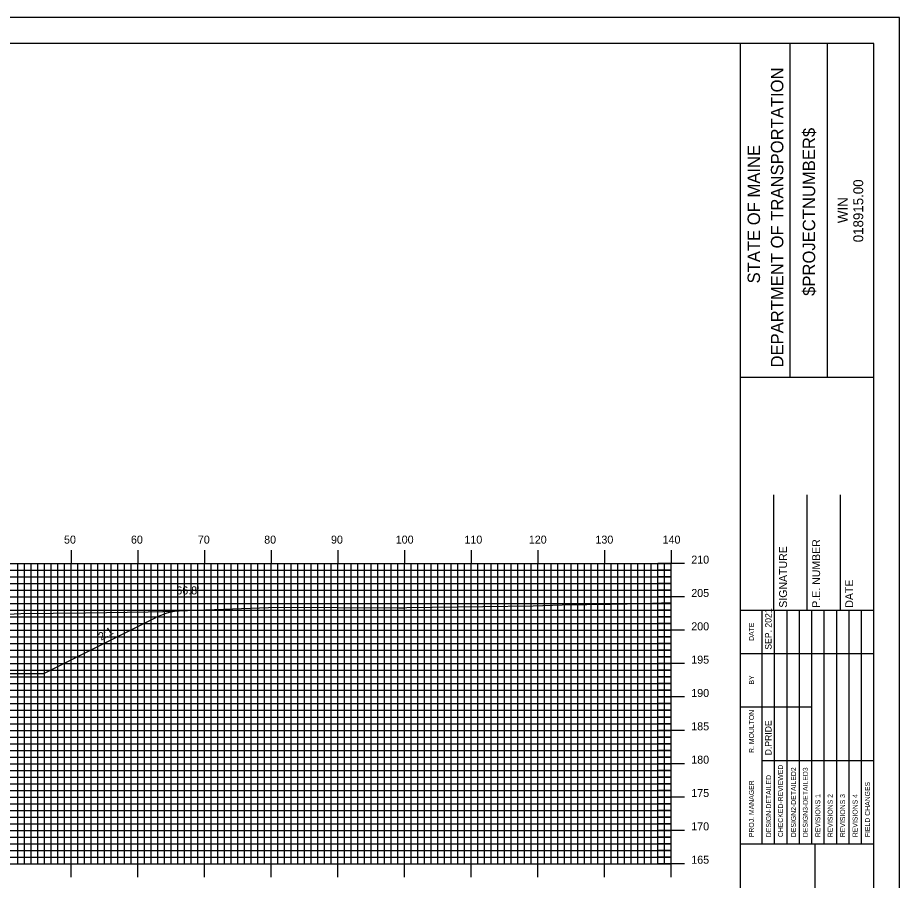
# Model space of a CAD drawing. Extents: x 1795240 to 1795583, y 442591 to 442811.
# Drawn here: x 1795447.3 to 1795579.6, y 442681.2 to 442810.5 of the extents above; entities that cross this region are included whole.
import ezdxf

# ---------------------------------------------------------------- set-up
doc = ezdxf.new("R2010")
doc.units = 0
for name, color, linetype in [('ANNOTATION', 7, 'Continuous'), ('BORDER', 7, 'Continuous'), ('D_Roadway_Centerline', 7, 'Continuous'), ('D_Roadway_SlopeLines', 7, 'Continuous'), ('D_Text_Standard', 7, 'Continuous'), ('H_V ANNOTATION', 7, 'Continuous'), ('MAJOR', 7, 'Continuous'), ('MINOR', 7, 'Continuous'), ('PLOT BOUNDARY', 7, 'Continuous'), ('S_Roadway_Centerline', 7, 'Continuous')]:
    doc.layers.add(name, color=color, linetype=linetype)

msp = doc.modelspace()

# ---------------------------------------------------------------- linework, layer by layer
at = {"layer": 'BORDER'}
for p, q in [((1795555.77, 442596.67), (1795555.77, 442806.67)), ((1795563.22, 442756.66), (1795563.22, 442806.66)), ((1795568.81, 442756.66), (1795568.81, 442806.66)), ((1795555.77, 442756.65), (1795575.77, 442756.65)), ((1795560.77, 442721.67), (1795560.77, 442738.97)), ((1795565.77, 442721.67), (1795565.77, 442738.97)), ((1795570.77, 442721.67), (1795570.77, 442738.97)), ((1795555.77, 442721.67), (1795575.77, 442721.67)), ((1795555.77, 442686.67), (1795575.77, 442686.67)), ((1795566.95, 442616.67), (1795566.95, 442686.67))]:
    msp.add_line(p, q, dxfattribs=at)
msp.add_lwpolyline([(1795255.77, 442596.67), (1795575.77, 442596.67), (1795575.77, 442806.67), (1795255.77, 442806.67)], close=True, dxfattribs=at)
for points in [[(1795559, 442715.17), (1795559, 442721.67)], [(1795560.86, 442686.68), (1795560.86, 442721.67)], [(1795562.72, 442721.67), (1795562.72, 442686.68)], [(1795564.59, 442686.68), (1795564.59, 442721.67)], [(1795566.45, 442686.68), (1795566.45, 442721.67)], [(1795568.31, 442686.68), (1795568.31, 442721.67)], [(1795570.18, 442686.68), (1795570.18, 442721.67)], [(1795572.04, 442686.68), (1795572.04, 442721.67)], [(1795573.9, 442686.68), (1795573.9, 442721.67)], [(1795559, 442686.68), (1795559, 442720.26)], [(1795555.77, 442715.17), (1795575.77, 442715.17)], [(1795555.77, 442707.17), (1795559, 442707.17)], [(1795559, 442707.17), (1795566.45, 442707.17)], [(1795559, 442699.17), (1795575.77, 442699.17)]]:
    msp.add_lwpolyline(points, dxfattribs=at)
at = {"layer": 'D_Roadway_Centerline'}
msp.add_arc((1795472.56, 442711.63), 10, 92.1706, 116.5651, dxfattribs=at)
at = {"layer": 'D_Roadway_SlopeLines'}
msp.add_line((1795451.28, 442712.17), (1795468.09, 442720.57), dxfattribs=at)
msp.add_lwpolyline([(1795444.37, 442708.53), (1795445.28, 442712.17), (1795451.28, 442712.17)], dxfattribs=at)
at = {"layer": 'MAJOR'}
for p, q in [((1795455.37, 442730.67), (1795455.37, 442728.67)), ((1795465.37, 442730.67), (1795465.37, 442728.67)), ((1795475.37, 442730.67), (1795475.37, 442728.67)), ((1795485.37, 442730.67), (1795485.37, 442728.67)), ((1795495.37, 442730.67), (1795495.37, 442728.67)), ((1795505.37, 442730.67), (1795505.37, 442728.67)), ((1795515.37, 442730.67), (1795515.37, 442728.67)), ((1795525.37, 442730.67), (1795525.37, 442728.67)), ((1795535.37, 442730.67), (1795535.37, 442728.67)), ((1795545.37, 442730.67), (1795545.37, 442728.67)), ((1795265.37, 442728.67), (1795545.37, 442728.67)), ((1795265.37, 442728.67), (1795545.37, 442728.67)), ((1795455.37, 442683.67), (1795455.37, 442728.67)), ((1795465.37, 442683.67), (1795465.37, 442728.67)), ((1795475.37, 442683.67), (1795475.37, 442728.67)), ((1795485.37, 442683.67), (1795485.37, 442728.67)), ((1795495.37, 442683.67), (1795495.37, 442728.67)), ((1795505.37, 442683.67), (1795505.37, 442728.67)), ((1795515.37, 442683.67), (1795515.37, 442728.67)), ((1795525.37, 442683.67), (1795525.37, 442728.67)), ((1795535.37, 442683.67), (1795535.37, 442728.67)), ((1795547.37, 442728.67), (1795543.36, 442728.67)), ((1795545.37, 442683.67), (1795545.37, 442728.67)), ((1795545.37, 442683.67), (1795545.37, 442728.67)), ((1795265.37, 442723.67), (1795545.37, 442723.67)), ((1795547.37, 442723.67), (1795543.36, 442723.67)), ((1795265.37, 442718.67), (1795545.37, 442718.67)), ((1795547.37, 442718.67), (1795543.36, 442718.67)), ((1795265.37, 442713.67), (1795545.37, 442713.67)), ((1795547.37, 442713.67), (1795543.36, 442713.67)), ((1795265.37, 442708.67), (1795545.37, 442708.67)), ((1795547.37, 442708.67), (1795543.36, 442708.67)), ((1795265.37, 442703.67), (1795545.37, 442703.67)), ((1795547.37, 442703.67), (1795543.36, 442703.67)), ((1795265.37, 442698.67), (1795545.37, 442698.67)), ((1795547.37, 442698.67), (1795543.36, 442698.67)), ((1795265.37, 442693.67), (1795545.37, 442693.67)), ((1795547.37, 442693.67), (1795543.36, 442693.67)), ((1795265.37, 442688.67), (1795545.37, 442688.67)), ((1795547.37, 442688.67), (1795543.36, 442688.67)), ((1795265.37, 442683.67), (1795545.37, 442683.67)), ((1795265.37, 442683.67), (1795545.37, 442683.67)), ((1795455.37, 442681.66), (1795455.37, 442683.67)), ((1795465.37, 442681.66), (1795465.37, 442683.67)), ((1795475.37, 442681.66), (1795475.37, 442683.67)), ((1795485.37, 442681.66), (1795485.37, 442683.67)), ((1795495.37, 442681.66), (1795495.37, 442683.67)), ((1795505.37, 442681.66), (1795505.37, 442683.67)), ((1795515.37, 442681.66), (1795515.37, 442683.67)), ((1795525.37, 442681.66), (1795525.37, 442683.67)), ((1795535.37, 442681.66), (1795535.37, 442683.67)), ((1795547.37, 442683.67), (1795543.36, 442683.67)), ((1795545.37, 442681.66), (1795545.37, 442683.67))]:
    msp.add_line(p, q, dxfattribs=at)
at = {"layer": 'MINOR'}
for p, q in [((1795447.37, 442683.67), (1795447.37, 442728.67)), ((1795448.37, 442683.67), (1795448.37, 442728.67)), ((1795449.37, 442683.67), (1795449.37, 442728.67)), ((1795450.37, 442683.67), (1795450.37, 442728.67)), ((1795451.37, 442683.67), (1795451.37, 442728.67)), ((1795452.37, 442683.67), (1795452.37, 442728.67)), ((1795453.37, 442683.67), (1795453.37, 442728.67)), ((1795454.37, 442683.67), (1795454.37, 442728.67)), ((1795456.37, 442683.67), (1795456.37, 442728.67)), ((1795457.37, 442683.67), (1795457.37, 442728.67)), ((1795458.37, 442683.67), (1795458.37, 442728.67)), ((1795459.37, 442683.67), (1795459.37, 442728.67)), ((1795460.37, 442683.67), (1795460.37, 442728.67)), ((1795461.37, 442683.67), (1795461.37, 442728.67)), ((1795462.37, 442683.67), (1795462.37, 442728.67)), ((1795463.37, 442683.67), (1795463.37, 442728.67)), ((1795464.37, 442683.67), (1795464.37, 442728.67)), ((1795466.37, 442683.67), (1795466.37, 442728.67)), ((1795467.37, 442683.67), (1795467.37, 442728.67)), ((1795468.37, 442683.67), (1795468.37, 442728.67)), ((1795469.37, 442683.67), (1795469.37, 442728.67)), ((1795470.37, 442683.67), (1795470.37, 442728.67)), ((1795471.37, 442683.67), (1795471.37, 442728.67)), ((1795472.37, 442683.67), (1795472.37, 442728.67)), ((1795473.37, 442683.67), (1795473.37, 442728.67)), ((1795474.37, 442683.67), (1795474.37, 442728.67)), ((1795476.37, 442683.67), (1795476.37, 442728.67)), ((1795477.37, 442683.67), (1795477.37, 442728.67)), ((1795478.37, 442683.67), (1795478.37, 442728.67)), ((1795479.37, 442683.67), (1795479.37, 442728.67)), ((1795480.37, 442683.67), (1795480.37, 442728.67)), ((1795481.37, 442683.67), (1795481.37, 442728.67)), ((1795482.37, 442683.67), (1795482.37, 442728.67)), ((1795483.37, 442683.67), (1795483.37, 442728.67)), ((1795484.37, 442683.67), (1795484.37, 442728.67)), ((1795486.37, 442683.67), (1795486.37, 442728.67)), ((1795487.37, 442683.67), (1795487.37, 442728.67)), ((1795488.37, 442683.67), (1795488.37, 442728.67)), ((1795489.37, 442683.67), (1795489.37, 442728.67)), ((1795490.37, 442683.67), (1795490.37, 442728.67)), ((1795491.37, 442683.67), (1795491.37, 442728.67)), ((1795492.37, 442683.67), (1795492.37, 442728.67)), ((1795493.37, 442683.67), (1795493.37, 442728.67)), ((1795494.37, 442683.67), (1795494.37, 442728.67)), ((1795496.37, 442683.67), (1795496.37, 442728.67)), ((1795497.37, 442683.67), (1795497.37, 442728.67)), ((1795498.37, 442683.67), (1795498.37, 442728.67)), ((1795499.37, 442683.67), (1795499.37, 442728.67)), ((1795500.37, 442683.67), (1795500.37, 442728.67)), ((1795501.37, 442683.67), (1795501.37, 442728.67)), ((1795502.37, 442683.67), (1795502.37, 442728.67)), ((1795503.37, 442683.67), (1795503.37, 442728.67)), ((1795504.37, 442683.67), (1795504.37, 442728.67)), ((1795506.37, 442683.67), (1795506.37, 442728.67)), ((1795507.37, 442683.67), (1795507.37, 442728.67)), ((1795508.37, 442683.67), (1795508.37, 442728.67)), ((1795509.37, 442683.67), (1795509.37, 442728.67)), ((1795510.37, 442683.67), (1795510.37, 442728.67)), ((1795511.37, 442683.67), (1795511.37, 442728.67)), ((1795512.37, 442683.67), (1795512.37, 442728.67)), ((1795513.37, 442683.67), (1795513.37, 442728.67)), ((1795514.37, 442683.67), (1795514.37, 442728.67)), ((1795516.37, 442683.67), (1795516.37, 442728.67)), ((1795517.37, 442683.67), (1795517.37, 442728.67)), ((1795518.37, 442683.67), (1795518.37, 442728.67)), ((1795519.37, 442683.67), (1795519.37, 442728.67)), ((1795520.37, 442683.67), (1795520.37, 442728.67)), ((1795521.37, 442683.67), (1795521.37, 442728.67)), ((1795522.37, 442683.67), (1795522.37, 442728.67)), ((1795523.37, 442683.67), (1795523.37, 442728.67)), ((1795524.37, 442683.67), (1795524.37, 442728.67)), ((1795526.37, 442683.67), (1795526.37, 442728.67)), ((1795527.37, 442683.67), (1795527.37, 442728.67)), ((1795528.37, 442683.67), (1795528.37, 442728.67)), ((1795529.37, 442683.67), (1795529.37, 442728.67)), ((1795530.37, 442683.67), (1795530.37, 442728.67)), ((1795531.37, 442683.67), (1795531.37, 442728.67)), ((1795532.37, 442683.67), (1795532.37, 442728.67)), ((1795533.37, 442683.67), (1795533.37, 442728.67)), ((1795534.37, 442683.67), (1795534.37, 442728.67)), ((1795536.37, 442683.67), (1795536.37, 442728.67)), ((1795537.37, 442683.67), (1795537.37, 442728.67)), ((1795538.37, 442683.67), (1795538.37, 442728.67)), ((1795539.37, 442683.67), (1795539.37, 442728.67)), ((1795540.37, 442683.67), (1795540.37, 442728.67)), ((1795541.37, 442683.67), (1795541.37, 442728.67)), ((1795542.37, 442683.67), (1795542.37, 442728.67)), ((1795543.37, 442683.67), (1795543.37, 442728.67)), ((1795544.37, 442683.67), (1795544.37, 442728.67)), ((1795265.37, 442727.67), (1795545.37, 442727.67)), ((1795545.37, 442727.67), (1795543.36, 442727.67)), ((1795265.37, 442726.67), (1795545.37, 442726.67)), ((1795545.37, 442726.67), (1795543.36, 442726.67)), ((1795265.37, 442725.67), (1795545.37, 442725.67)), ((1795545.37, 442725.67), (1795543.36, 442725.67)), ((1795265.37, 442724.67), (1795545.37, 442724.67)), ((1795545.37, 442724.67), (1795543.36, 442724.67)), ((1795265.37, 442722.67), (1795545.37, 442722.67)), ((1795545.37, 442722.67), (1795543.36, 442722.67)), ((1795265.37, 442721.67), (1795545.37, 442721.67)), ((1795545.37, 442721.67), (1795543.36, 442721.67)), ((1795265.37, 442720.67), (1795545.37, 442720.67)), ((1795265.37, 442719.67), (1795545.37, 442719.67)), ((1795545.37, 442720.67), (1795543.36, 442720.67)), ((1795545.37, 442719.67), (1795543.36, 442719.67)), ((1795265.37, 442717.67), (1795545.37, 442717.67)), ((1795545.37, 442717.67), (1795543.36, 442717.67)), ((1795265.37, 442716.67), (1795545.37, 442716.67)), ((1795265.37, 442715.67), (1795545.37, 442715.67)), ((1795545.37, 442716.67), (1795543.36, 442716.67)), ((1795545.37, 442715.67), (1795543.36, 442715.67)), ((1795265.37, 442714.67), (1795545.37, 442714.67)), ((1795545.37, 442714.67), (1795543.36, 442714.67)), ((1795265.37, 442712.67), (1795545.37, 442712.67)), ((1795265.37, 442711.67), (1795545.37, 442711.67)), ((1795545.37, 442712.67), (1795543.36, 442712.67)), ((1795545.37, 442711.67), (1795543.36, 442711.67)), ((1795265.37, 442710.67), (1795545.37, 442710.67)), ((1795545.37, 442710.67), (1795543.36, 442710.67)), ((1795265.37, 442709.67), (1795545.37, 442709.67)), ((1795545.37, 442709.67), (1795543.36, 442709.67)), ((1795265.37, 442707.67), (1795545.37, 442707.67)), ((1795545.37, 442707.67), (1795543.36, 442707.67)), ((1795265.37, 442706.67), (1795545.37, 442706.67)), ((1795545.37, 442706.67), (1795543.36, 442706.67)), ((1795265.37, 442705.67), (1795545.37, 442705.67)), ((1795545.37, 442705.67), (1795543.36, 442705.67)), ((1795265.37, 442704.67), (1795545.37, 442704.67)), ((1795545.37, 442704.67), (1795543.36, 442704.67)), ((1795265.37, 442702.67), (1795545.37, 442702.67)), ((1795545.37, 442702.67), (1795543.36, 442702.67)), ((1795265.37, 442701.67), (1795545.37, 442701.67)), ((1795545.37, 442701.67), (1795543.36, 442701.67)), ((1795265.37, 442700.67), (1795545.37, 442700.67)), ((1795265.37, 442699.67), (1795545.37, 442699.67)), ((1795545.37, 442700.67), (1795543.36, 442700.67)), ((1795545.37, 442699.67), (1795543.36, 442699.67)), ((1795265.37, 442697.67), (1795545.37, 442697.67)), ((1795545.37, 442697.67), (1795543.36, 442697.67)), ((1795265.37, 442696.67), (1795545.37, 442696.67)), ((1795265.37, 442695.67), (1795545.37, 442695.67)), ((1795545.37, 442696.67), (1795543.36, 442696.67)), ((1795545.37, 442695.67), (1795543.36, 442695.67)), ((1795265.37, 442694.67), (1795545.37, 442694.67)), ((1795545.37, 442694.67), (1795543.36, 442694.67)), ((1795265.37, 442692.67), (1795545.37, 442692.67)), ((1795265.37, 442691.67), (1795545.37, 442691.67)), ((1795545.37, 442692.67), (1795543.36, 442692.67)), ((1795545.37, 442691.67), (1795543.36, 442691.67)), ((1795265.37, 442690.67), (1795545.37, 442690.67)), ((1795545.37, 442690.67), (1795543.36, 442690.67)), ((1795265.37, 442689.67), (1795545.37, 442689.67)), ((1795545.37, 442689.67), (1795543.36, 442689.67)), ((1795265.37, 442687.67), (1795545.37, 442687.67)), ((1795545.37, 442687.67), (1795543.36, 442687.67)), ((1795265.37, 442686.67), (1795545.37, 442686.67)), ((1795545.37, 442686.67), (1795543.36, 442686.67)), ((1795265.37, 442685.67), (1795545.37, 442685.67)), ((1795545.37, 442685.67), (1795543.36, 442685.67)), ((1795265.37, 442684.67), (1795545.37, 442684.67)), ((1795545.37, 442684.67), (1795543.36, 442684.67))]:
    msp.add_line(p, q, dxfattribs=at)
at = {"layer": 'PLOT BOUNDARY'}
msp.add_lwpolyline([(1795239.58, 442590.55), (1795579.58, 442590.55), (1795579.58, 442810.55), (1795239.58, 442810.55)], close=True, dxfattribs=at)
at = {"layer": 'S_Roadway_Centerline'}
msp.add_lwpolyline([(1795441.79, 442720.91), (1795447.8, 442721.17), (1795457.51, 442721.29), (1795466.9, 442721.45), (1795469.13, 442721.48), (1795472.84, 442721.65), (1795486.34, 442722.16), (1795504.53, 442722.06), (1795505.27, 442722.06), (1795505.72, 442722.07), (1795517.12, 442722.24), (1795524.64, 442722.33), (1795529, 442722.47), (1795536.42, 442722.59), (1795541.15, 442722.71), (1795543.89, 442722.78), (1795545.37, 442722.78)], dxfattribs=at)

# ---------------------------------------------------------------- texts
at = {"layer": 'ANNOTATION'}
msp.add_text('2:1', height=1.2, rotation=29.7449, dxfattribs=at).set_placement((1795459.87, 442717.1))
msp.add_text('2:1', height=1.2, rotation=29.7449, dxfattribs=at).set_placement((1795459.87, 442717.1))
at = {"layer": 'BORDER'}
for s, height, p in [('DEPARTMENT OF TRANSPORTATION', 1.8635, (1795562.18, 442758.08)), ('$PROJECTNUMBER$', 1.8635, (1795566.95, 442768.82)), ('STATE OF MAINE', 1.8635, (1795558.68, 442770.69)), ('018915.00', 1.491, (1795574.16, 442776.86)), ('WIN', 1.491, (1795571.84, 442779.73)), ('P.E. NUMBER', 1.1811, (1795567.69, 442722.06)), ('SIGNATURE', 1.181, (1795562.73, 442722.06)), ('DATE', 1.181, (1795572.65, 442722.06)), ('SEP. 2021', 0.969, (1795560.41, 442715.76)), ('DATE', 0.743, (1795557.77, 442717.08)), ('BY', 0.743, (1795557.77, 442710.54)), ('R. MOULTON', 0.745, (1795557.78, 442700.28)), ('D.PRIDE', 0.969, (1795560.41, 442699.92)), ('CHECKED-REVIEWED', 0.7455, (1795562.13, 442687.65)), ('DESIGN2-DETAILED2', 0.7455, (1795564.07, 442687.65)), ('DESIGN3-DETAILED3', 0.7455, (1795565.85, 442687.65)), ('PROJ. MANAGER', 0.7455, (1795557.77, 442687.65)), ('DESIGN-DETAILED', 0.7455, (1795560.34, 442687.65)), ('FIELD CHANGES', 0.7455, (1795575.17, 442687.65)), ('REVISIONS 1', 0.7455, (1795567.72, 442687.65)), ('REVISIONS 2', 0.7455, (1795569.58, 442687.65)), ('REVISIONS 3', 0.7455, (1795571.44, 442687.65)), ('REVISIONS 4', 0.7455, (1795573.31, 442687.65))]:
    msp.add_text(s, height=height, rotation=90, dxfattribs=at).set_placement(p)
at = {"layer": 'D_Text_Standard'}
msp.add_text("66.8'", height=1.2, dxfattribs=at).set_placement((1795471.14, 442724.05))
at = {"layer": 'H_V ANNOTATION'}
for s, p in [('50', (1795454.3, 442731.67)), ('60', (1795464.34, 442731.67)), ('70', (1795474.37, 442731.67)), ('80', (1795484.32, 442731.67)), ('90', (1795494.34, 442731.67)), ('100', (1795504.05, 442731.67)), ('110', (1795514.35, 442731.67)), ('120', (1795524.01, 442731.67)), ('130', (1795534, 442731.67)), ('140', (1795544.07, 442731.67)), ('210', (1795548.37, 442728.67)), ('205', (1795548.37, 442723.67)), ('200', (1795548.37, 442718.67)), ('195', (1795548.37, 442713.67)), ('190', (1795548.37, 442708.67)), ('185', (1795548.37, 442703.67)), ('180', (1795548.37, 442698.67)), ('175', (1795548.37, 442693.67)), ('170', (1795548.37, 442688.67)), ('165', (1795548.37, 442683.67))]:
    msp.add_text(s, height=1.2, dxfattribs=at).set_placement(p)

doc.saveas('drawing.dxf')
